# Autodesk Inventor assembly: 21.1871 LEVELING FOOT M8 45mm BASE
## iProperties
Created: 2007-03
Part Number: 21.1871 LEVELING FOOT M8 45mm BASE
Document SubType Name: Assembly
Designer: Andy Moles
Author: Andy Moles
